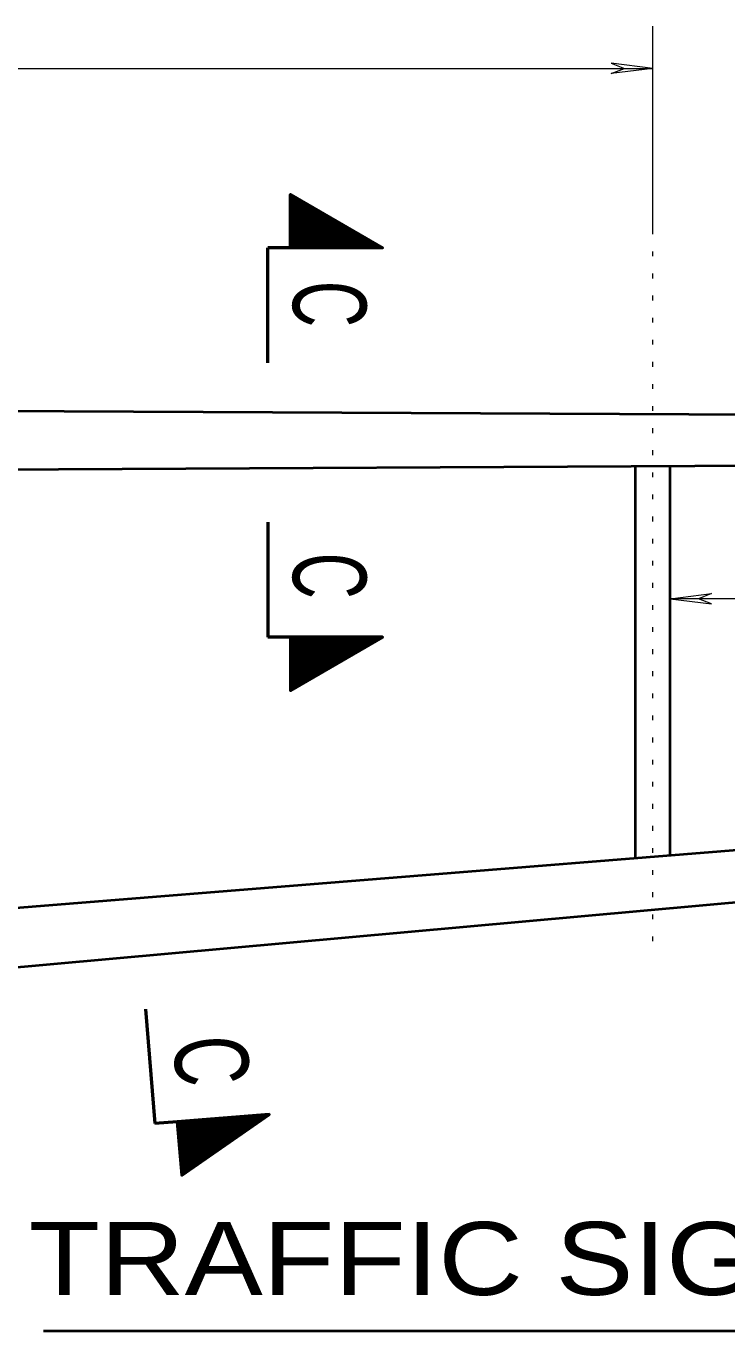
# Model space of a CAD drawing. Extents: x 312583 to 312854, y 144419 to 144597.
# Drawn here: x 312759.83 to 312774.43, y 144538.41 to 144565.58 of the extents above; entities that cross this region are included whole.
import ezdxf
from ezdxf.enums import TextEntityAlignment as Align

# ---------------------------------------------------------------- set-up
doc = ezdxf.new("R2010")
doc.units = 0
doc.header["$LTSCALE"] = 0.3
doc.linetypes.add('DOTTED', pattern=[1.5, 0.3, -1.2])
doc.layers.add('1', color=7, linetype='Continuous', lineweight=35)
doc.layers.add('2', color=7, linetype='Continuous', lineweight=13)

msp = doc.modelspace()

# ---------------------------------------------------------------- linework, layer by layer
at = {"layer": '1'}
for p, q in [((312765.3432, 144562.0416), (312765.3586, 144562.0569)), ((312765.3432, 144561.9956), (312765.3816, 144562.0493)), ((312765.3432, 144561.9419), (312765.3969, 144562.0339)), ((312765.3432, 144561.8959), (312765.4199, 144562.0186)), ((312765.3432, 144561.8423), (312765.4429, 144562.0109)), ((312765.3432, 144561.8039), (312765.4582, 144561.9956)), ((312765.3432, 144561.7503), (312765.4812, 144561.9879)), ((312765.3432, 144561.7043), (312765.5042, 144561.9726)), ((312765.3432, 144561.6583), (312765.5196, 144561.9649)), ((312765.3432, 144561.6123), (312765.5502, 144561.9496)), ((312765.3432, 144561.5586), (312765.5656, 144561.9419)), ((312765.3432, 144561.5126), (312765.5886, 144561.9266)), ((312765.3432, 144561.4666), (312765.6116, 144561.9189)), ((312765.3432, 144561.4129), (312765.6269, 144561.9036)), ((312765.3432, 144561.3669), (312765.6499, 144561.8959)), ((312765.3432, 144561.3209), (312765.6652, 144561.8806)), ((312765.3432, 144561.2673), (312765.6882, 144561.8653)), ((312765.3432, 144561.2213), (312765.7112, 144561.8576)), ((312765.3432, 144561.1753), (312765.7266, 144561.8423)), ((312765.3432, 144561.1293), (312765.7496, 144561.8269)), ((312765.3432, 144561.0756), (312765.7726, 144561.8193)), ((312765.3432, 144561.0373), (312765.7879, 144561.8039)), ((312765.3432, 144560.9836), (312765.8186, 144561.7963)), ((312765.3586, 144560.9606), (312765.8339, 144561.7809)), ((312765.3892, 144560.9606), (312765.8569, 144561.7733)), ((312765.4199, 144560.9606), (312765.8799, 144561.7579)), ((312765.4429, 144560.9606), (312765.8952, 144561.7503)), ((312765.4736, 144560.9606), (312765.9182, 144561.7349)), ((312765.4966, 144560.9683), (312765.9412, 144561.7273)), ((312765.5272, 144560.9683), (312765.9566, 144561.7119)), ((312765.5502, 144560.9606), (312765.9796, 144561.7043)), ((312765.5809, 144560.9606), (312766.0026, 144561.6889)), ((312765.6116, 144560.9606), (312766.0179, 144561.6736)), ((312765.6346, 144560.9606), (312766.0409, 144561.6659)), ((312765.6652, 144560.9606), (312766.0639, 144561.6506)), ((312765.6959, 144560.9606), (312766.0869, 144561.6353)), ((312765.7189, 144560.9606), (312766.1022, 144561.6276)), ((312765.7496, 144560.9683), (312766.1252, 144561.6123)), ((312765.7802, 144560.9606), (312766.1482, 144561.6046)), ((312765.8032, 144560.9606), (312766.1636, 144561.5893)), ((312765.8262, 144560.9606), (312766.1866, 144561.5816)), ((312765.8569, 144560.9606), (312766.2096, 144561.5663)), ((312765.8876, 144560.9606), (312766.2249, 144561.5586)), ((312765.9182, 144560.9606), (312766.2479, 144561.5433)), ((312765.9412, 144560.9606), (312766.2709, 144561.5356)), ((312765.9719, 144560.9606), (312766.2862, 144561.5203)), ((312765.9949, 144560.9683), (312766.3169, 144561.5126)), ((312766.0256, 144560.9606), (312766.3322, 144561.4973)), ((312766.0486, 144560.9606), (312766.3552, 144561.4819)), ((312766.0792, 144560.9606), (312766.3782, 144561.4743)), ((312766.1099, 144560.9606), (312766.3936, 144561.4589)), ((312766.1329, 144560.9606), (312766.4166, 144561.4513)), ((312766.1636, 144560.9606), (312766.4396, 144561.4359)), ((312766.1942, 144560.9606), (312766.4549, 144561.4283)), ((312766.2172, 144560.9606), (312766.4779, 144561.4129)), ((312766.2479, 144560.9606), (312766.5009, 144561.4053)), ((312766.2786, 144560.9606), (312766.5162, 144561.3899)), ((312766.3016, 144560.9606), (312766.5392, 144561.3823)), ((312766.3246, 144560.9606), (312766.5622, 144561.3669)), ((312766.3552, 144560.9606), (312766.5852, 144561.3593)), ((312766.3859, 144560.9606), (312766.6006, 144561.3439)), ((312766.4166, 144560.9606), (312766.6236, 144561.3286)), ((312766.4396, 144560.9606), (312766.6466, 144561.3209)), ((312766.4702, 144560.9606), (312766.6619, 144561.3056)), ((312766.4932, 144560.9606), (312766.6849, 144561.2903)), ((312766.5239, 144560.9606), (312766.7079, 144561.2826)), ((312766.5469, 144560.9606), (312766.7232, 144561.2673)), ((312766.5776, 144560.9606), (312766.7462, 144561.2596)), ((312766.6082, 144560.9606), (312766.7692, 144561.2443)), ((312766.6312, 144560.9606), (312766.7846, 144561.2366)), ((312766.6619, 144560.9606), (312766.8152, 144561.2213)), ((312766.6849, 144560.9606), (312766.8306, 144561.2136)), ((312766.7156, 144560.9606), (312766.8536, 144561.1983)), ((312766.7462, 144560.9606), (312766.8766, 144561.1906)), ((312766.7692, 144560.9606), (312766.8919, 144561.1753)), ((312766.7999, 144560.9606), (312766.9149, 144561.1676)), ((312766.8229, 144560.9606), (312766.9379, 144561.1523)), ((312766.8536, 144560.9606), (312766.9532, 144561.1369)), ((312766.8842, 144560.9606), (312766.9762, 144561.1293)), ((312766.9149, 144560.9606), (312766.9992, 144561.1139)), ((312766.9379, 144560.9606), (312767.0146, 144561.0986)), ((312766.9686, 144560.9606), (312767.0376, 144561.0909)), ((312766.9916, 144560.9606), (312767.0606, 144561.0756)), ((312767.0146, 144560.9606), (312767.0836, 144561.0679)), ((312767.0452, 144560.9606), (312767.0989, 144561.0526)), ((312767.0759, 144560.9606), (312767.1219, 144561.0449)), ((312767.1066, 144560.9606), (312767.1449, 144561.0296)), ((312767.1296, 144560.9606), (312767.1602, 144561.0219)), ((312767.1602, 144560.9606), (312767.1832, 144561.0066)), ((312767.1832, 144560.9606), (312767.2062, 144560.9989)), ((312767.2139, 144560.9606), (312767.2216, 144560.9836)), ((312767.2446, 144560.9606), (312767.2446, 144560.9759)), ((312765.3432, 144552.8339), (312765.8186, 144552.0213)), ((312765.3586, 144552.8569), (312765.8339, 144552.0366)), ((312765.3892, 144552.8569), (312765.8569, 144552.0443)), ((312765.4199, 144552.8569), (312765.8799, 144552.0596)), ((312765.4429, 144552.8569), (312765.8952, 144552.0673)), ((312765.4736, 144552.8569), (312765.9182, 144552.0826)), ((312765.4966, 144552.8493), (312765.9412, 144552.0903)), ((312765.5272, 144552.8493), (312765.9566, 144552.1056)), ((312765.5502, 144552.8569), (312765.9796, 144552.1133)), ((312765.5809, 144552.8569), (312766.0026, 144552.1286)), ((312765.6116, 144552.8569), (312766.0179, 144552.1439)), ((312765.6346, 144552.8569), (312766.0409, 144552.1516)), ((312765.6652, 144552.8569), (312766.0639, 144552.1669)), ((312765.6959, 144552.8569), (312766.0869, 144552.1823)), ((312765.7189, 144552.8569), (312766.1022, 144552.1899)), ((312765.7496, 144552.8493), (312766.1252, 144552.2053)), ((312765.7802, 144552.8569), (312766.1482, 144552.2129)), ((312765.8032, 144552.8569), (312766.1636, 144552.2283)), ((312765.8262, 144552.8569), (312766.1866, 144552.2359)), ((312765.8569, 144552.8569), (312766.2096, 144552.2513)), ((312765.8876, 144552.8569), (312766.2249, 144552.2589)), ((312765.9182, 144552.8569), (312766.2479, 144552.2743)), ((312765.9412, 144552.8569), (312766.2709, 144552.2819)), ((312765.9719, 144552.8569), (312766.2862, 144552.2973)), ((312765.9949, 144552.8493), (312766.3169, 144552.3049)), ((312766.0256, 144552.8569), (312766.3322, 144552.3203)), ((312766.0486, 144552.8569), (312766.3552, 144552.3356)), ((312766.0792, 144552.8569), (312766.3782, 144552.3433)), ((312766.1099, 144552.8569), (312766.3936, 144552.3586)), ((312766.1329, 144552.8569), (312766.4166, 144552.3663)), ((312766.1636, 144552.8569), (312766.4396, 144552.3816)), ((312766.1942, 144552.8569), (312766.4549, 144552.3893)), ((312766.2172, 144552.8569), (312766.4779, 144552.4046)), ((312766.2479, 144552.8569), (312766.5009, 144552.4123)), ((312766.2786, 144552.8569), (312766.5162, 144552.4276)), ((312766.3016, 144552.8569), (312766.5392, 144552.4353)), ((312766.3246, 144552.8569), (312766.5622, 144552.4506)), ((312766.3552, 144552.8569), (312766.5852, 144552.4583)), ((312766.3859, 144552.8569), (312766.6006, 144552.4736)), ((312766.4166, 144552.8569), (312766.6236, 144552.4889)), ((312766.4396, 144552.8569), (312766.6466, 144552.4966)), ((312766.4702, 144552.8569), (312766.6619, 144552.5119)), ((312766.4932, 144552.8569), (312766.6849, 144552.5273)), ((312766.5239, 144552.8569), (312766.7079, 144552.5349)), ((312766.5469, 144552.8569), (312766.7232, 144552.5503)), ((312766.5776, 144552.8569), (312766.7462, 144552.5579)), ((312766.6082, 144552.8569), (312766.7692, 144552.5733)), ((312766.6312, 144552.8569), (312766.7846, 144552.5809)), ((312766.6619, 144552.8569), (312766.8152, 144552.5963)), ((312766.6849, 144552.8569), (312766.8306, 144552.6039)), ((312766.7156, 144552.8569), (312766.8536, 144552.6193)), ((312766.7462, 144552.8569), (312766.8766, 144552.6269)), ((312766.7692, 144552.8569), (312766.8919, 144552.6423)), ((312766.7999, 144552.8569), (312766.9149, 144552.6499)), ((312766.8229, 144552.8569), (312766.9379, 144552.6653)), ((312766.8536, 144552.8569), (312766.9532, 144552.6806)), ((312766.8842, 144552.8569), (312766.9762, 144552.6883)), ((312766.9149, 144552.8569), (312766.9992, 144552.7036)), ((312766.9379, 144552.8569), (312767.0146, 144552.7189)), ((312766.9686, 144552.8569), (312767.0376, 144552.7266)), ((312766.9916, 144552.8569), (312767.0606, 144552.7419)), ((312767.0146, 144552.8569), (312767.0836, 144552.7496)), ((312767.0452, 144552.8569), (312767.0989, 144552.7649)), ((312767.0759, 144552.8569), (312767.1219, 144552.7726)), ((312767.1066, 144552.8569), (312767.1449, 144552.7879)), ((312767.1296, 144552.8569), (312767.1602, 144552.7956)), ((312767.1602, 144552.8569), (312767.1832, 144552.8109)), ((312767.1832, 144552.8569), (312767.2062, 144552.8186)), ((312767.2139, 144552.8569), (312767.2216, 144552.8339)), ((312767.2446, 144552.8569), (312767.2446, 144552.8416)), ((312765.3432, 144552.7803), (312765.7879, 144552.0136)), ((312765.3432, 144552.7419), (312765.7726, 144551.9983)), ((312765.3432, 144552.6883), (312765.7496, 144551.9906)), ((312765.3432, 144552.6423), (312765.7266, 144551.9753)), ((312765.3432, 144552.5963), (312765.7112, 144551.9599)), ((312765.3432, 144552.5503), (312765.6882, 144551.9523)), ((312765.3432, 144552.4966), (312765.6652, 144551.9369)), ((312765.3432, 144552.4506), (312765.6499, 144551.9216)), ((312765.3432, 144552.4046), (312765.6269, 144551.9139)), ((312765.3432, 144552.3509), (312765.6116, 144551.8986)), ((312765.3432, 144552.3049), (312765.5886, 144551.8909)), ((312765.3432, 144552.2589), (312765.5656, 144551.8756)), ((312765.3432, 144552.2053), (312765.5502, 144551.8679)), ((312765.3432, 144552.1593), (312765.5196, 144551.8526)), ((312765.3432, 144552.1133), (312765.5042, 144551.8449)), ((312765.3432, 144552.0673), (312765.4812, 144551.8296)), ((312765.3432, 144552.0136), (312765.4582, 144551.8219)), ((312765.3432, 144551.9753), (312765.4429, 144551.8066)), ((312765.3432, 144551.9216), (312765.4199, 144551.7989)), ((312765.3432, 144551.8756), (312765.3969, 144551.7836)), ((312765.3432, 144551.8219), (312765.3816, 144551.7683)), ((312765.3432, 144551.7759), (312765.3586, 144551.7606)), ((312762.9896, 144542.7446), (312763.5262, 144541.9703)), ((312762.9972, 144542.7676), (312763.5416, 144541.9856)), ((312763.0279, 144542.7753), (312763.5646, 144542.0009)), ((312763.0586, 144542.7753), (312763.5799, 144542.0163)), ((312763.0816, 144542.7753), (312763.5952, 144542.0239)), ((312763.1122, 144542.7753), (312763.6182, 144542.0393)), ((312763.1352, 144542.7753), (312763.6412, 144542.0546)), ((312763.1659, 144542.7753), (312763.6566, 144542.0699)), ((312763.1889, 144542.7829), (312763.6796, 144542.0776)), ((312763.2196, 144542.7829), (312763.7026, 144542.0929)), ((312763.2502, 144542.7906), (312763.7102, 144542.1083)), ((312763.2732, 144542.7906), (312763.7332, 144542.1236)), ((312763.3039, 144542.7906), (312763.7562, 144542.1389)), ((312763.3346, 144542.7983), (312763.7792, 144542.1543)), ((312763.3576, 144542.7983), (312763.7946, 144542.1619)), ((312763.3882, 144542.7906), (312763.8176, 144542.1773)), ((312763.4189, 144542.8059), (312763.8406, 144542.1926)), ((312763.4419, 144542.8059), (312763.8559, 144542.2079)), ((312763.4649, 144542.8059), (312763.8712, 144542.2156)), ((312763.4956, 144542.8059), (312763.8942, 144542.2309)), ((312763.5262, 144542.8136), (312763.9096, 144542.2386)), ((312763.5569, 144542.8136), (312763.9326, 144542.2616)), ((312763.5799, 144542.8136), (312763.9556, 144542.2693)), ((312763.6106, 144542.8213), (312763.9709, 144542.2846)), ((312763.6336, 144542.8136), (312764.0016, 144542.2923)), ((312763.6642, 144542.8213), (312764.0169, 144542.3153)), ((312763.6872, 144542.8213), (312764.0322, 144542.3306)), ((312763.7179, 144542.8289), (312764.0552, 144542.3383)), ((312763.7486, 144542.8289), (312764.0706, 144542.3536)), ((312763.7716, 144542.8289), (312764.0936, 144542.3613)), ((312763.8022, 144542.8366), (312764.1166, 144542.3843)), ((312763.8329, 144542.8366), (312764.1319, 144542.3919)), ((312763.8559, 144542.8366), (312764.1549, 144542.4073)), ((312763.8866, 144542.8366), (312764.1702, 144542.4149)), ((312763.9172, 144542.8443), (312764.1856, 144542.4303)), ((312763.9402, 144542.8443), (312764.2086, 144542.4456)), ((312763.9632, 144542.8443), (312764.2316, 144542.4609)), ((312763.9939, 144542.8519), (312764.2546, 144542.4686)), ((312764.0246, 144542.8519), (312764.2699, 144542.4839)), ((312764.0552, 144542.8519), (312764.2929, 144542.4993)), ((312764.0782, 144542.8519), (312764.3159, 144542.5146)), ((312764.1089, 144542.8596), (312764.3236, 144542.5299)), ((312764.1319, 144542.8596), (312764.3466, 144542.5453)), ((312764.1626, 144542.8596), (312764.3696, 144542.5529)), ((312764.1856, 144542.8673), (312764.3849, 144542.5683)), ((312764.2162, 144542.8673), (312764.4079, 144542.5836)), ((312764.2469, 144542.8673), (312764.4309, 144542.5989)), ((312764.2699, 144542.8673), (312764.4462, 144542.6066)), ((312764.3006, 144542.8749), (312764.4692, 144542.6219)), ((312764.3236, 144542.8749), (312764.4846, 144542.6373)), ((312764.3542, 144542.8749), (312764.5076, 144542.6526)), ((312764.3849, 144542.8826), (312764.5306, 144542.6603)), ((312764.4079, 144542.8826), (312764.5459, 144542.6756)), ((312764.4386, 144542.8826), (312764.5689, 144542.6833)), ((312764.4616, 144542.8826), (312764.5919, 144542.7063)), ((312764.4922, 144542.8903), (312764.5996, 144542.7216)), ((312764.5229, 144542.8903), (312764.6226, 144542.7293)), ((312764.5536, 144542.8903), (312764.6456, 144542.7446)), ((312764.5766, 144542.8979), (312764.6609, 144542.7599)), ((312764.6072, 144542.8979), (312764.6839, 144542.7753)), ((312764.6302, 144542.8979), (312764.7069, 144542.7906)), ((312764.6532, 144542.8979), (312764.7299, 144542.7983)), ((312764.6839, 144542.9056), (312764.7452, 144542.8136)), ((312764.7146, 144542.9056), (312764.7606, 144542.8289)), ((312764.7452, 144542.9056), (312764.7836, 144542.8443)), ((312764.7682, 144542.9133), (312764.7989, 144542.8519)), ((312764.7989, 144542.9133), (312764.8219, 144542.8673)), ((312764.8219, 144542.9133), (312764.8449, 144542.8749)), ((312764.8526, 144542.9209), (312764.8602, 144542.8979)), ((312764.8832, 144542.9209), (312764.8832, 144542.9056)), ((312762.9896, 144542.6909), (312763.4956, 144541.9626)), ((312762.9972, 144542.6526), (312763.4802, 144541.9473)), ((312762.9972, 144542.5989), (312763.4572, 144541.9396)), ((312763.0049, 144542.5529), (312763.4342, 144541.9166)), ((312763.0049, 144542.5069), (312763.4266, 144541.9013)), ((312763.0126, 144542.4609), (312763.4036, 144541.8936)), ((312763.0126, 144542.4073), (312763.3806, 144541.8783)), ((312763.0202, 144542.3613), (312763.3652, 144541.8629)), ((312763.0202, 144542.3153), (312763.3422, 144541.8476)), ((312763.0279, 144542.2616), (312763.3269, 144541.8323)), ((312763.0279, 144542.2156), (312763.3039, 144541.8246)), ((312763.0356, 144542.1696), (312763.2809, 144541.8093)), ((312763.0356, 144542.1159), (312763.2732, 144541.8016)), ((312763.0432, 144542.0699), (312763.2426, 144541.7786)), ((312763.0432, 144542.0239), (312763.2272, 144541.7709)), ((312763.0509, 144541.9779), (312763.2042, 144541.7556)), ((312763.0509, 144541.9243), (312763.1812, 144541.7479)), ((312763.0509, 144541.8859), (312763.1659, 144541.7249)), ((312763.0586, 144541.8323), (312763.1429, 144541.7173)), ((312763.0662, 144541.7863), (312763.1199, 144541.7019)), ((312763.0662, 144541.7326), (312763.1122, 144541.6866)), ((312763.0739, 144541.6866), (312763.0892, 144541.6789))]:
    msp.add_line(p, q, dxfattribs=at)
at = {"layer": '1', "linetype": 'DOTTED', "lineweight": 13}
msp.add_line((312772.8872, 144546.5243), (312772.8872, 144561.2443), dxfattribs=at)
at = {"layer": '1', "lineweight": 53}
for p, q in [((312764.8679, 144558.5686), (312764.8679, 144560.9606)), ((312765.3432, 144560.9606), (312764.8679, 144560.9606)), ((312764.8679, 144555.2489), (312764.8679, 144552.8569)), ((312765.3432, 144552.8569), (312764.8679, 144552.8569)), ((312762.3226, 144545.1136), (312762.5142, 144542.7293)), ((312762.9819, 144542.7676), (312762.5142, 144542.7293))]:
    msp.add_line(p, q, dxfattribs=at)
at = {"layer": '1', "lineweight": 40}
for p, q in [((312712.2132, 144557.8019), (312791.0956, 144557.4109)), ((312791.0956, 144556.4986), (312712.2132, 144556.1076)), ((312772.5269, 144548.2569), (312772.5269, 144556.4066)), ((312773.2476, 144548.3183), (312773.2476, 144556.4143)), ((312712.2132, 144543.4269), (312791.0956, 144549.7443)), ((312712.2209, 144541.6943), (312791.0956, 144548.8319))]:
    msp.add_line(p, q, dxfattribs=at)
at = {"layer": '1', "lineweight": 53}
for points in [[(312765.3432, 144560.9606), (312765.3432, 144562.0723), (312767.2599, 144560.9606)], [(312765.3432, 144552.8569), (312765.3432, 144551.7453), (312767.2599, 144552.8569)], [(312762.9819, 144542.7676), (312763.0739, 144541.6559), (312764.8986, 144542.9209)]]:
    msp.add_lwpolyline(points, close=True, dxfattribs=at)
at = {"layer": '2'}
for p, q in [((312772.8872, 144561.2443), (312772.8872, 144565.5759)), ((312772.0209, 144564.8016), (312772.2969, 144564.6943)), ((312772.8872, 144564.6943), (312772.0209, 144564.8016)), ((312772.0209, 144564.5869), (312772.2969, 144564.6943)), ((312772.8872, 144564.6943), (312772.0209, 144564.5869)), ((312773.2476, 144553.6543), (312774.1139, 144553.7616)), ((312775.7546, 144553.6543), (312773.2476, 144553.6543)), ((312773.2476, 144553.6543), (312774.1139, 144553.5469)), ((312774.1139, 144553.7616), (312773.8379, 144553.6543)), ((312774.1139, 144553.5469), (312773.8379, 144553.6543))]:
    msp.add_line(p, q, dxfattribs=at)
at = {"layer": '2', "lineweight": 40}
msp.add_line((312760.1944, 144538.4129), (312815.3652, 144538.4129), dxfattribs=at)
at = {"layer": '2'}
msp.add_lwpolyline([(312710.5956, 144564.6943), (312741.7376, 144564.6943), (312772.8872, 144564.6943)], dxfattribs=at)

# ---------------------------------------------------------------- texts
at = {"layer": '1'}
for rotation, width, p in [(270.003, 0.65, (312765.3892, 144559.7913)), (270.003, 0.65, (312765.3892, 144554.1333)), (274.577, 0.7, (312762.9324, 144543.9767))]:
    msp.add_text('C', height=1.533, rotation=rotation, dxfattribs=dict(at, width=width)).set_placement(p, align=Align.CENTER)
at = {"layer": '2', "width": 1.2}
msp.add_text('TRAFFIC SIGNAL MAST ARM - TROMBONE TYPE ', height=1.52, dxfattribs=at).set_placement((312759.8843, 144539.1606))

doc.saveas('drawing.dxf')
